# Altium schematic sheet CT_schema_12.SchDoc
size 389 x 278 mm
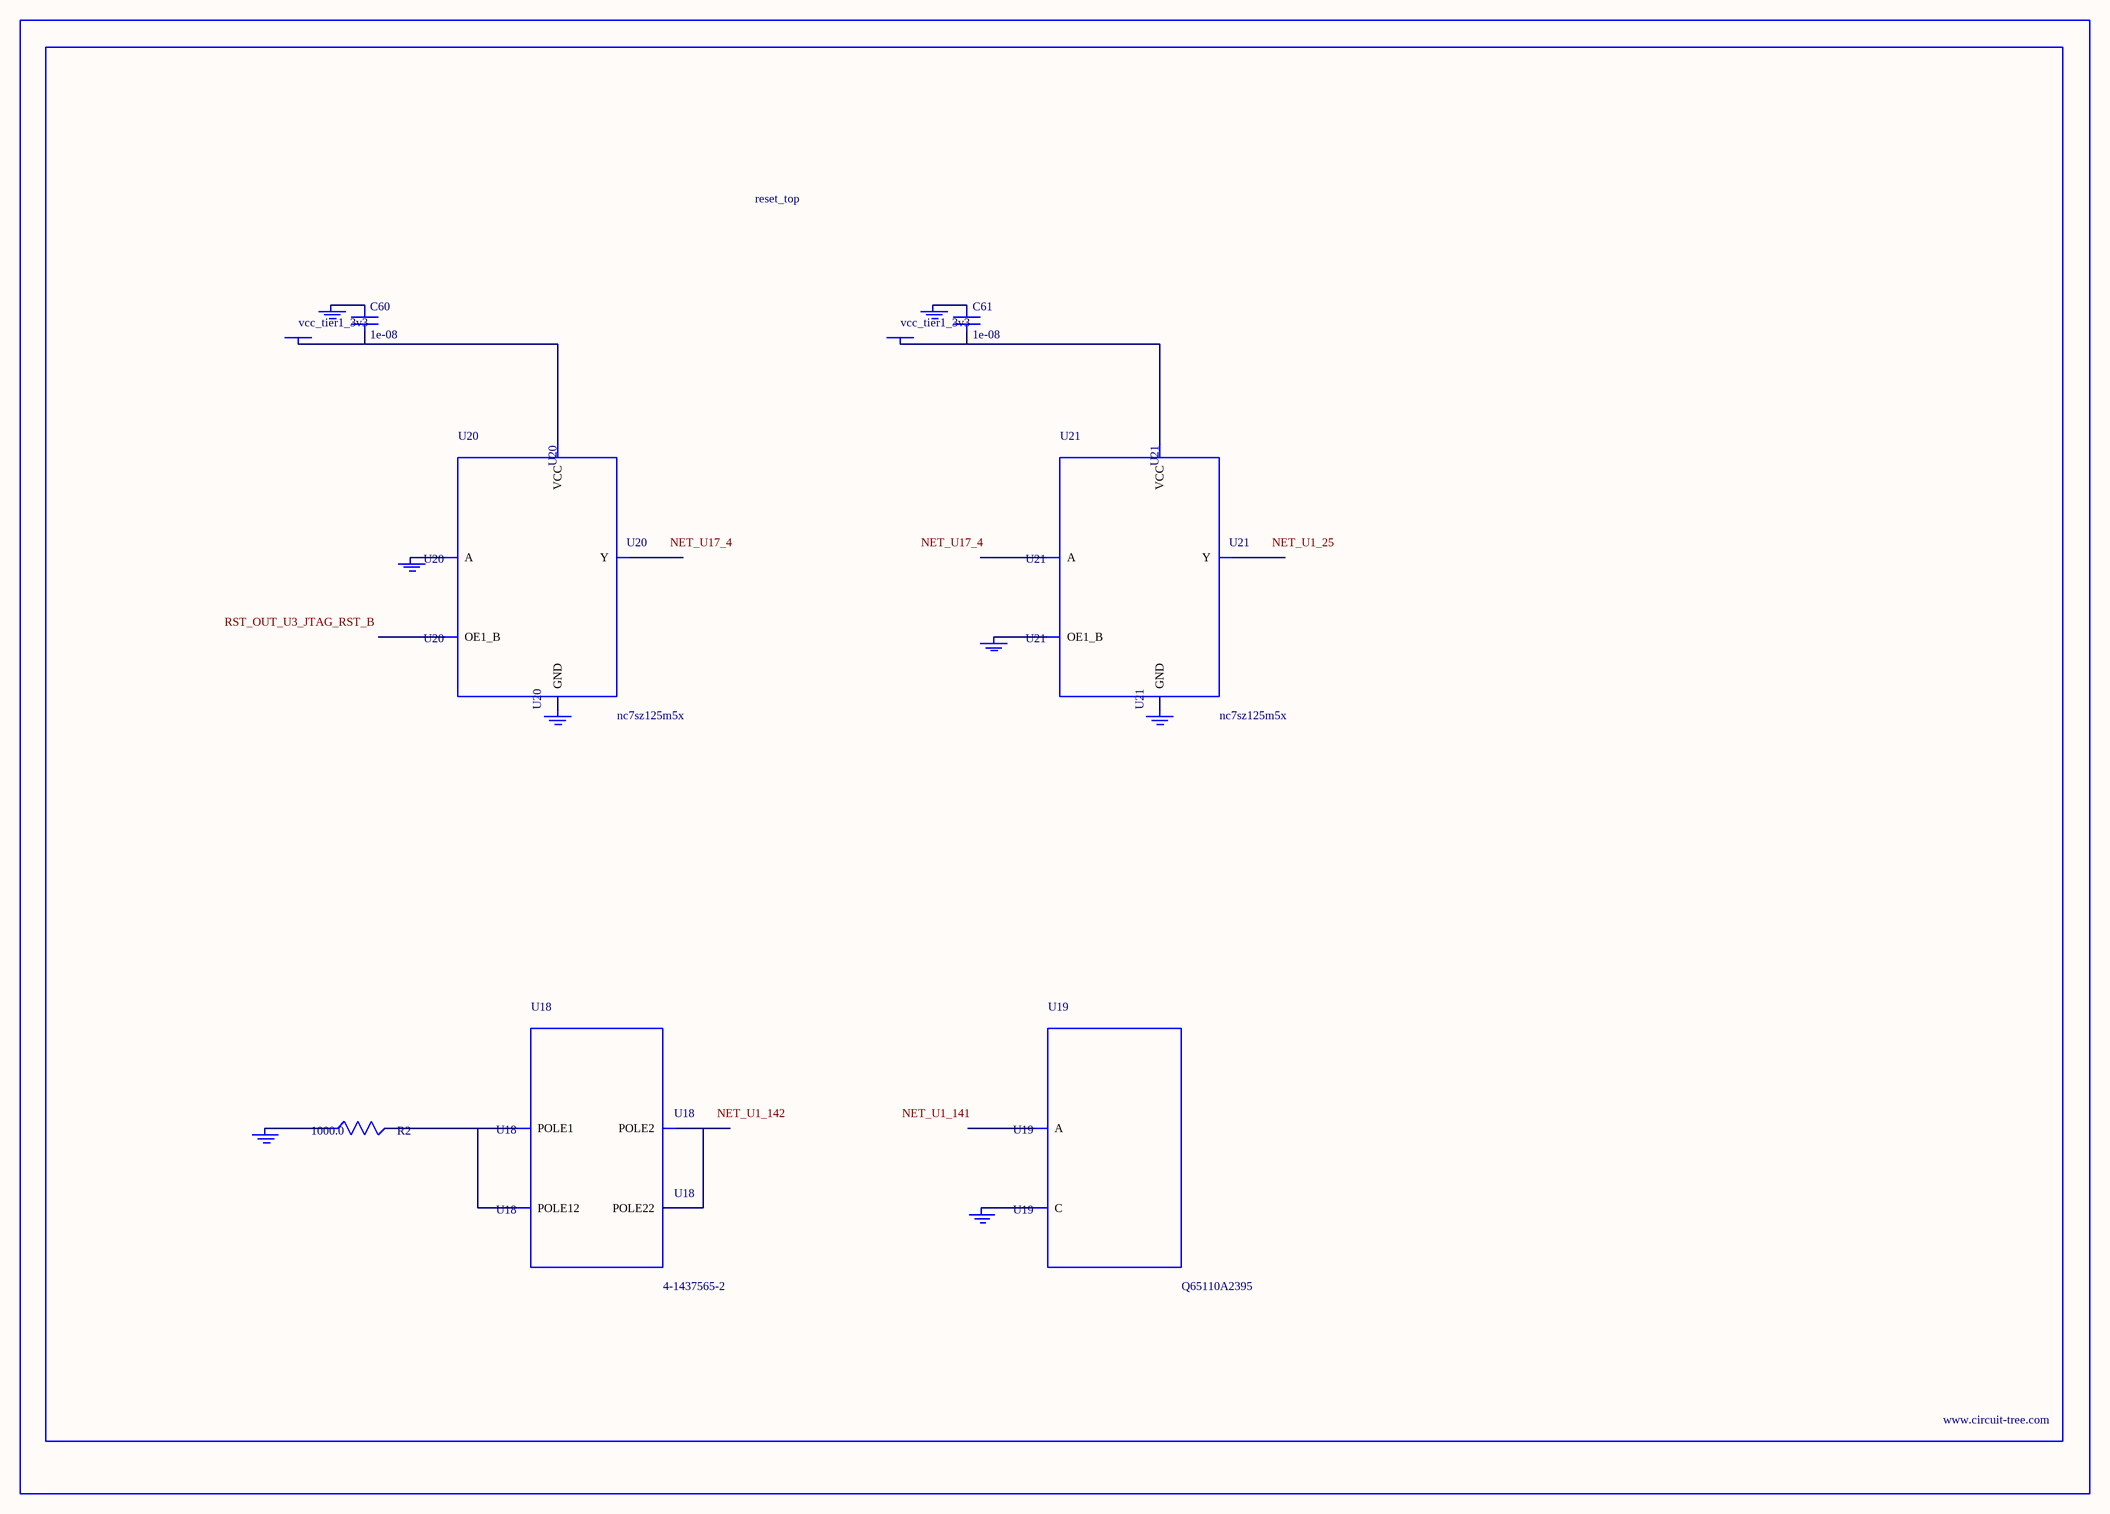
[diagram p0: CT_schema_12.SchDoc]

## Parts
BORDER11  (no value)
C60  1e-08  [C0402]
C61  1e-08  [C0402]
GND_INSTANCE_11_0  (no value)
GND_INSTANCE_11_1  (no value)
GND_INSTANCE_11_2  (no value)
GND_INSTANCE_11_3  (no value)
GND_INSTANCE_11_4  (no value)
GND_INSTANCE_11_5  (no value)
GND_INSTANCE_11_6  (no value)
GND_INSTANCE_11_7  (no value)
POWER_INSTANCE_11_0  vcc_tier1_3v3
POWER_INSTANCE_11_1  vcc_tier1_3v3
R2  1000.0  [R0603]
U18  4-1437565-2  [SW_4-1437565-2]
U19  Q65110A2395  [LGM67K-G1J2-24-Z]
U20  nc7sz125m5x  [NC7SZ125M5X]
U21  nc7sz125m5x  [NC7SZ125M5X]

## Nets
NetC60_1: C60.1 GND_INSTANCE_11_2.0(GND)
NetC60_2: C60.2 POWER_INSTANCE_11_0.0(PWR) U20.5(VCC)
NetC61_1: C61.1 GND_INSTANCE_11_5.0(GND)
NetC61_2: C61.2 POWER_INSTANCE_11_1.0(PWR) U21.5(VCC)
NetGND_INSTANCE_11_0_0: GND_INSTANCE_11_0.0(GND) R2.1
NetGND_INSTANCE_11_1_0: GND_INSTANCE_11_1.0(GND) U19.C
NetGND_INSTANCE_11_3_0: GND_INSTANCE_11_3.0(GND) U20.2(A)
NetGND_INSTANCE_11_4_0: GND_INSTANCE_11_4.0(GND) U20.3(GND)
NetGND_INSTANCE_11_6_0: GND_INSTANCE_11_6.0(GND) U21.1(OE1_B)
NetGND_INSTANCE_11_7_0: GND_INSTANCE_11_7.0(GND) U21.3(GND)
NetR2_2: R2.2 U18.1(POLE1) U18.2(POLE12)
NetU18_3: U18.3(POLE2) U18.4(POLE22)

Not connected (* = marked no-connect by the designer): U19 A; U20 1(OE1_B) 4(Y); U21 2(A) 4(Y)

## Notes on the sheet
- Labels drawn without touching a wire or pin: NET_U1_25, NET_U1_141, NET_U1_142, NET_U17_4, RST_OUT_U3_JTAG_RST_B

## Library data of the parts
BORDER11 = BORDER_PAGE11
C60 C61 = C0402C103K3RAC
GND_INSTANCE_11_0-GND_INSTANCE_11_7 = GND
POWER_INSTANCE_11_0 POWER_INSTANCE_11_1 = PWR
R2 = RC0603JR-071KL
